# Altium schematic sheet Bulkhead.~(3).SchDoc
size B; Organization: Monterey Bay Aquarium Research Institute; Address1: 7700 Sandholdt Rd; Address2: Moss Landing, CA 95039-9644; CompanyName: MBARI
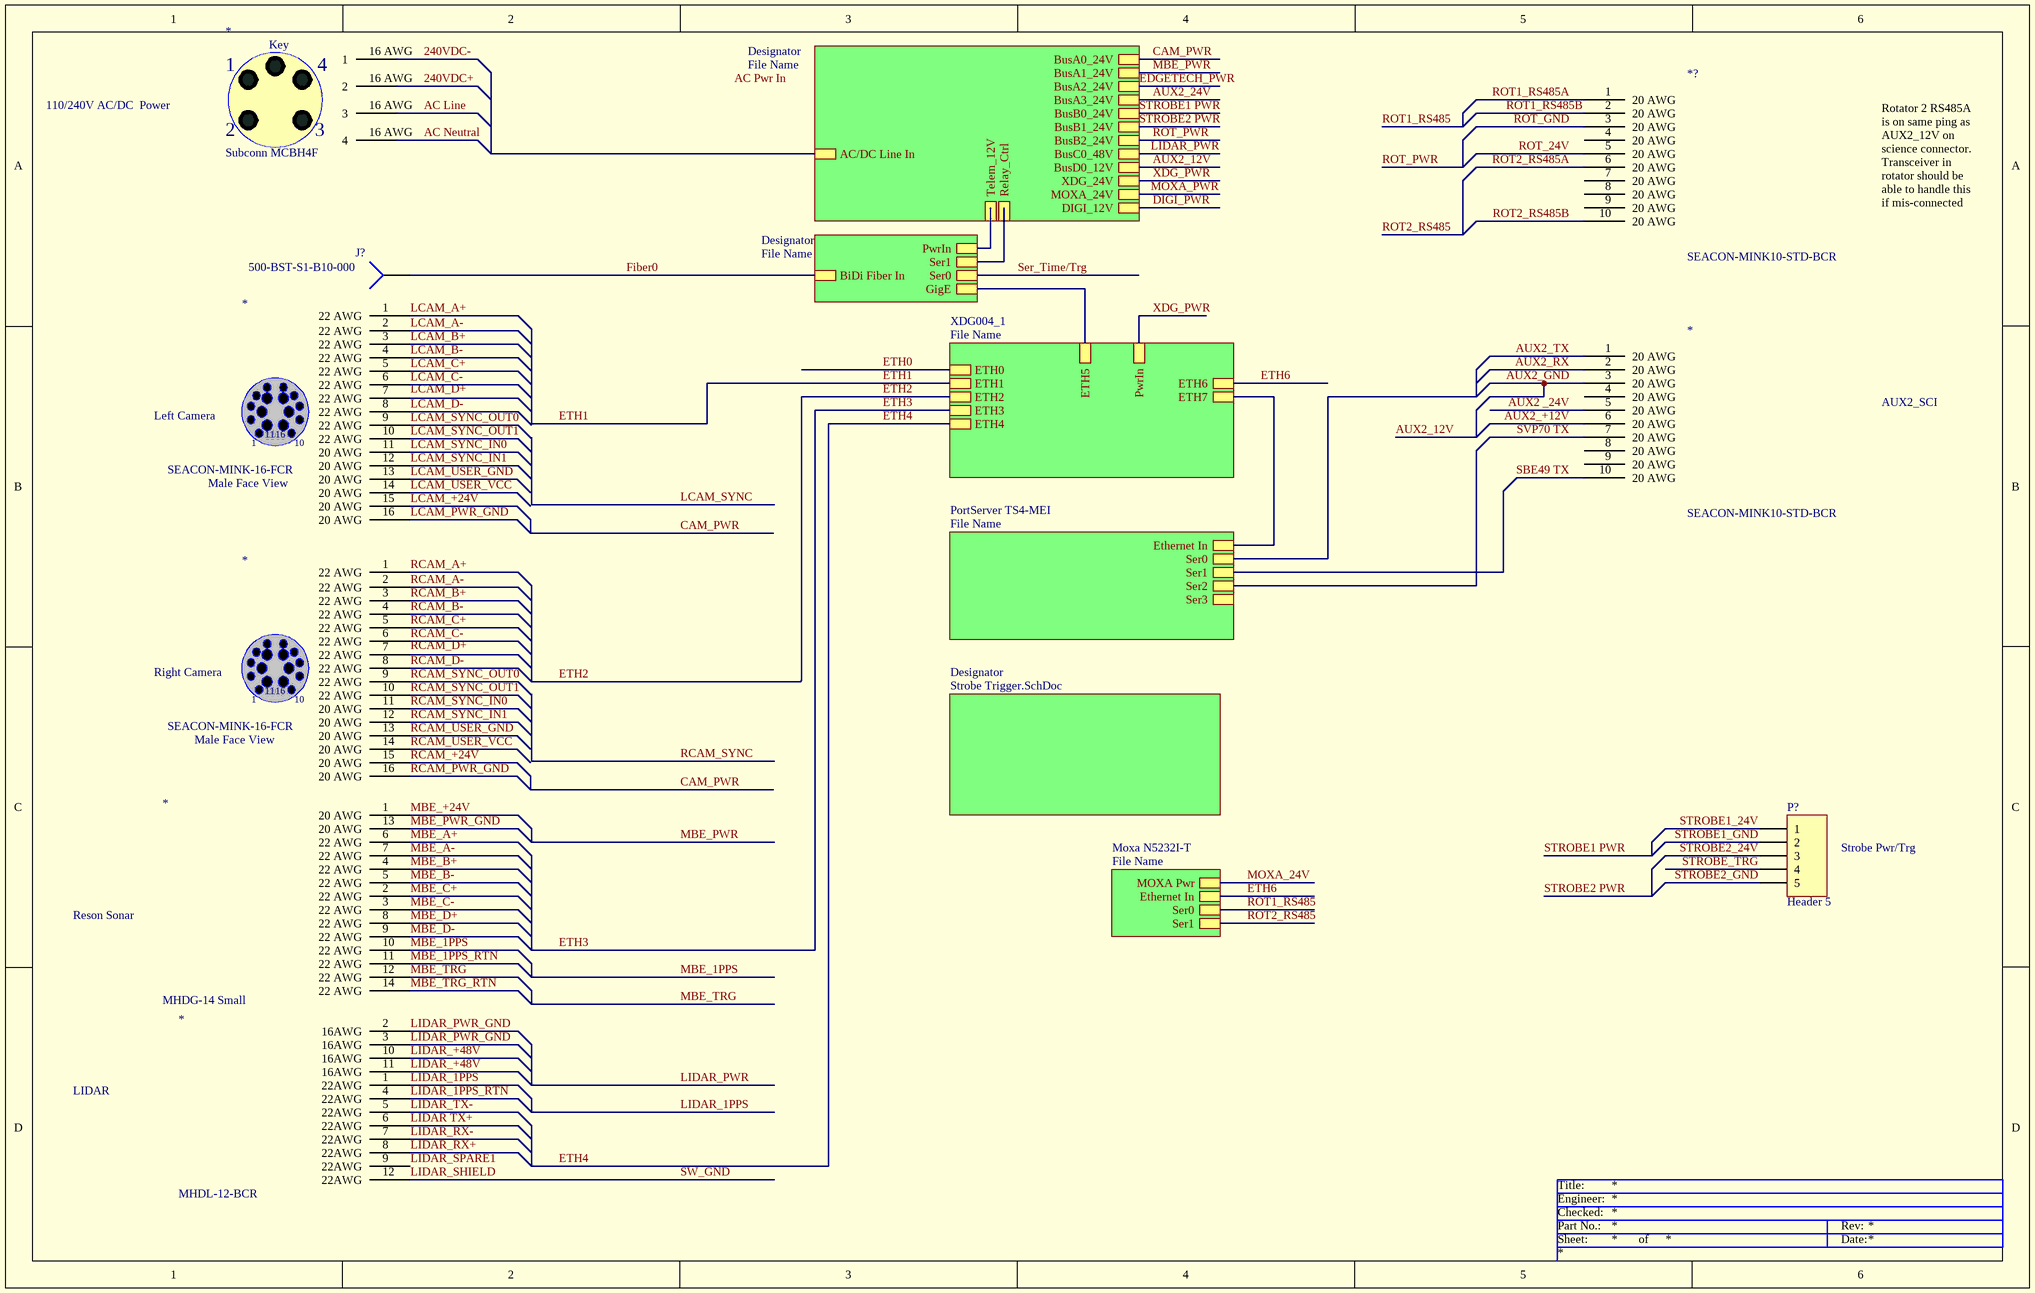
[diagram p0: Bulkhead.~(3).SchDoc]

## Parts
(Parts that share a designator on the sheet are numbered #1, #2 ... from top to bottom, then left to right.)
*#1  Subconn MCBH4F
*#2  SEACON-MINK-16-FCR
*#3  SEACON-MINK10-STD-BCR
*#4  SEACON-MINK-16-FCR
*#5  MHDG-14 Small
*#6  MHDL-12-BCR
*?  SEACON-MINK10-STD-BCR
J?  500-BST-S1-B10-000  [PIN1]
P?  Header 5  [HDR1X5]

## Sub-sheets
Designator = File Name: AC/DC Line In, BusA0_24V, BusA1_24V, BusC0_48V, BusA2_24V, BusA3_24V, BusD0_12V, Telem_12V, Relay_Ctrl, BusB1_24V, BusB2_24V, XDG_24V, MOXA_24V, DIGI_12V, BusB0_24V
Designator = File Name: BiDi Fiber In, GigE, Ser0, Ser1, PwrIn
Designator = Strobe Trigger.SchDoc: no entries
Moxa N5232I-T = File Name: Ethernet In, Ser0, Ser1, MOXA Pwr
PortServer TS4-MEI = File Name: Ethernet In, Ser0, Ser1, Ser2, Ser3
XDG004_1 = File Name: ETH0, ETH1, ETH2, ETH3, ETH4, ETH5, ETH6, ETH7, PwrIn

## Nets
240VDC+: *#1.16_AWG(2)
240VDC-: *#1.16_AWG(1)
AC Line: *#1.16_AWG(3)
AC Neutral: *#1.16_AWG(4)
AUX2 _24V: *#3.5(20_AWG)
AUX2_+12V: *#3.6(20_AWG)
AUX2_GND: *#3.3(20_AWG)
AUX2_RX: *#3.2(20_AWG)
AUX2_TX: *#3.1(20_AWG)
Fiber0: J?.1 ; sheet Designator/BiDi Fiber In
LCAM_+24V: *#2.15(20_AWG)
LCAM_A+: *#2.1(22_AWG)
LCAM_A-: *#2.2(22_AWG)
LCAM_B+: *#2.3(22_AWG)
LCAM_B-: *#2.4(22_AWG)
LCAM_C+: *#2.5(22_AWG)
LCAM_C-: *#2.6(22_AWG)
LCAM_D-: *#2.8(22_AWG)
LCAM_PWR_GND: *#2.16(20_AWG)
LCAM_SYNC_IN0: *#2.11(20_AWG)
LCAM_SYNC_IN1: *#2.12(20_AWG)
LCAM_SYNC_OUT0: *#2.9(22_AWG)
LCAM_SYNC_OUT1: *#2.10(22_AWG)
LCAM_USER_GND: *#2.13(20_AWG)
LCAM_USER_VCC: *#2.14(20_AWG)
LIDAR TX+: *#6.6(22AWG)
LIDAR_1PPS: *#6.1(22AWG)
LIDAR_1PPS_RTN: *#6.4(22AWG)
LIDAR_+48V: *#6.10(16AWG) *#6.11(16AWG)
LIDAR_PWR_GND: *#6.2(16AWG) *#6.3(16AWG)
LIDAR_RX+: *#6.8(22AWG)
LIDAR_RX-: *#6.7(22AWG)
LIDAR_SHIELD: *#6.12(22AWG)  [also labelled SW_GND]
LIDAR_SPARE1: *#6.9(22AWG)
LIDAR_TX-: *#6.5(22AWG)
MBE_1PPS: *#5.10(22_AWG)
MBE_1PPS_RTN: *#5.11(22_AWG)
MBE_+24V: *#5.1(20_AWG)
MBE_A+: *#5.6(22_AWG)
MBE_A-: *#5.7(22_AWG)
MBE_B+: *#5.4(22_AWG)
MBE_B-: *#5.5(22_AWG)
MBE_C+: *#5.2(22_AWG)
MBE_C-: *#5.3(22_AWG)
MBE_D+: *#5.8(22_AWG)
MBE_D-: *#5.9(22_AWG)
MBE_PWR_GND: *#5.13(20_AWG)
MBE_TRG: *#5.12(22_AWG)
MBE_TRG_RTN: *#5.14(22_AWG)
RCAM_+24V: *#4.15(20_AWG)
RCAM_A+: *#4.1(22_AWG)
RCAM_A-: *#4.2(22_AWG)
RCAM_B+: *#4.3(22_AWG)
RCAM_B-: *#4.4(22_AWG)
RCAM_C+: *#4.5(22_AWG)
RCAM_C-: *#4.6(22_AWG)
RCAM_D-: *#4.8(22_AWG)
RCAM_PWR_GND: *#4.16(20_AWG)
RCAM_SYNC_IN0: *#4.11(20_AWG)
RCAM_SYNC_IN1: *#4.12(20_AWG)
RCAM_SYNC_OUT0: *#4.9(22_AWG)
RCAM_SYNC_OUT1: *#4.10(22_AWG)
RCAM_USER_GND: *#4.13(20_AWG)
RCAM_USER_VCC: *#4.14(20_AWG)
ROT1_RS485A: *?.1(20_AWG)
ROT1_RS485B: *?.2(20_AWG)
ROT2_RS485A: *?.6(20_AWG)
ROT2_RS485B: *?.10(20_AWG)
ROT_24V: *?.5(20_AWG)
ROT_GND: *?.3(20_AWG)
SBE49 TX: *#3.10(20_AWG)
STROBE1_24V: P?.1
STROBE1_GND: P?.2
STROBE2_24V: P?.3
STROBE2_GND: P?.5
STROBE_TRG: P?.4
SVP70 TX: *#3.7(20_AWG)

Not connected (* = marked no-connect by the designer): *#2 7(22_AWG); *#3 4(20_AWG) 8(20_AWG) 9(20_AWG); *#4 7(22_AWG); *? 4(20_AWG) 7(20_AWG) 8(20_AWG) 9(20_AWG)

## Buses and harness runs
bus AUX2_12V
bus AUX2_12V = sheet Designator/BusD0_12V
bus AUX2_24V  = sheet Designator/BusA3_24V
bus CAM_PWR
bus CAM_PWR = sheet Designator/BusA0_24V
bus DIGI_PWR = sheet Designator/DIGI_12V
bus EDGETECH_PWR = sheet Designator/BusA2_24V
bus ETH0 = sheet XDG004_1/ETH0
bus ETH1 = sheet XDG004_1/ETH1
bus ETH2 = sheet XDG004_1/ETH2
bus ETH3 = sheet XDG004_1/ETH3
bus ETH4 = sheet XDG004_1/ETH4
bus ETH6 = sheet Moxa N5232I-T/Ethernet In
bus ETH6 = sheet XDG004_1/ETH6
bus LCAM_SYNC
bus LIDAR_1PPS
bus LIDAR_PWR
bus LIDAR_PWR = sheet Designator/BusC0_48V
bus MBE_1PPS
bus MBE_PWR
bus MBE_PWR = sheet Designator/BusA1_24V
bus MBE_TRG
bus MOXA_24V = sheet Moxa N5232I-T/MOXA Pwr
bus MOXA_PWR = sheet Designator/MOXA_24V
bus RCAM_SYNC
bus ROT1_RS485
bus ROT1_RS485 = sheet Moxa N5232I-T/Ser0
bus ROT2_RS485
bus ROT2_RS485 = sheet Moxa N5232I-T/Ser1
bus ROT_PWR
bus ROT_PWR = sheet Designator/BusB2_24V
bus Ser_Time/Trg = sheet Designator/Ser0
bus sheet Designator/GigE = sheet XDG004_1/ETH5
bus sheet Designator/PwrIn = sheet Designator/Telem_12V
bus sheet Designator/Relay_Ctrl = sheet Designator/Ser1
bus sheet PortServer TS4-MEI/Ethernet In = sheet XDG004_1/ETH7
bus STROBE1 PWR
bus STROBE1 PWR = sheet Designator/BusB0_24V
bus STROBE2 PWR
bus STROBE2 PWR = sheet Designator/BusB1_24V
bus XDG_PWR = sheet Designator/XDG_24V
bus XDG_PWR = sheet XDG004_1/PwrIn

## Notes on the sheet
- 110/240V AC/DC  Power
- Rotator 2 RS485A is on same ping as AUX2_12V on science connector. Transceiver in rotator should be able to handle this if mis-connected
- Left Camera
- AUX2_SCI
- Male Face View
- Right Camera
- Strobe Pwr/Trg
- Reson Sonar
- LIDAR
- Labels drawn without touching a wire or pin: AC Pwr In, LCAM_D+, RCAM_D+

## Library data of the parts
*#1 = Subconn MCIL4F: Subconn MCIL4F Connector
*#2 *#4 = SEACON-MINK-16-FCR: Seacon MINK-16 FCR
*#3 *? = SEACON-MINK10-STD-BCR: Seacon MINK10 BCR Standard Length
*#6 = MHDL-12-BCR: Impulse MHDL12 BCR
J? = Socket
P? = Header 5: Header, 5-Pin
